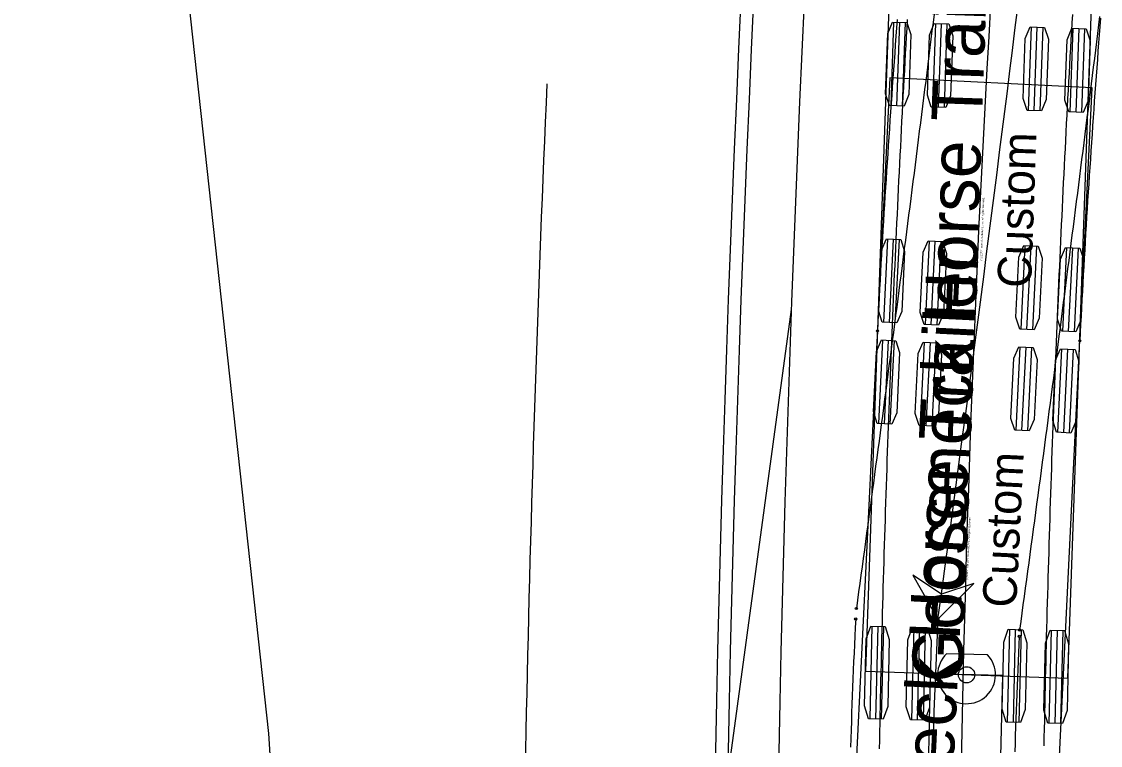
# Model space of a CAD drawing. Extents: x -14 to 1565148, y -25 to 642856.
# Drawn here: x 1564745.69 to 1564788.3, y 636164.84 to 636193.41 of the extents above; entities that cross this region are included whole.
import ezdxf

# ---------------------------------------------------------------- set-up
doc = ezdxf.new("R2010")
doc.units = 0
for name, color, linetype in [('CM_Corridor_Key_Station', 7, 'Continuous'), ('DR_P_Underdrain', 7, 'Continuous'), ('PV_P_EOP', 7, 'Continuous'), ('PV_X_EOP', 7, 'Continuous'), ('SC_Scratch15', 7, 'Continuous'), ('SC_Scratch2', 7, 'Continuous'), ('TR_Turning_Path24', 7, 'Continuous')]:
    doc.layers.add(name, color=color, linetype=linetype)

msp = doc.modelspace()

# ---------------------------------------------------------------- linework, layer by layer
at = {"layer": 'CM_Corridor_Key_Station'}
for p, q in [((1564779.982, 636191.188), (1564778.215, 636155.232)), ((1564787.972, 636190.795), (1564779.982, 636191.188)), ((1564786.206, 636154.839), (1564787.972, 636190.795)), ((1564779.737, 636181.539), (1564779.899, 636184.835)), ((1564779.966, 636181.527), (1564780.128, 636184.823)), ((1564780.195, 636181.516), (1564780.357, 636184.812)), ((1564781.385, 636181.458), (1564781.547, 636184.754)), ((1564781.614, 636181.446), (1564781.776, 636184.742)), ((1564781.843, 636181.435), (1564782.005, 636184.731)), ((1564785.164, 636181.272), (1564785.326, 636184.568)), ((1564785.393, 636181.261), (1564785.555, 636184.557)), ((1564785.622, 636181.249), (1564785.784, 636184.545)), ((1564786.812, 636181.191), (1564786.974, 636184.487)), ((1564787.041, 636181.18), (1564787.203, 636184.476)), ((1564787.27, 636181.168), (1564787.432, 636184.464)), ((1564779.541, 636177.543), (1564779.703, 636180.839)), ((1564779.77, 636177.532), (1564779.932, 636180.828)), ((1564779.999, 636177.521), (1564780.161, 636180.817)), ((1564781.189, 636177.462), (1564781.351, 636180.758)), ((1564781.418, 636177.451), (1564781.58, 636180.747)), ((1564781.647, 636177.44), (1564781.809, 636180.736)), ((1564784.968, 636177.277), (1564785.13, 636180.573)), ((1564785.197, 636177.265), (1564785.359, 636180.561)), ((1564785.426, 636177.254), (1564785.587, 636180.55)), ((1564786.616, 636177.196), (1564786.778, 636180.492)), ((1564786.845, 636177.184), (1564787.007, 636180.48)), ((1564787.074, 636177.173), (1564787.236, 636180.469))]:
    msp.add_line(p, q, dxfattribs=at)
for points in [[(1564781.726, 636193.711), (1564781.685, 636193.38), (1564781.644, 636193.049), (1564781.602, 636192.718), (1564781.561, 636192.388), (1564781.519, 636192.057), (1564781.478, 636191.726), (1564781.437, 636191.395), (1564781.395, 636191.064), (1564781.353, 636190.734), (1564781.312, 636190.403), (1564781.27, 636190.072), (1564781.228, 636189.741), (1564781.186, 636189.411), (1564781.144, 636189.08), (1564781.102, 636188.749), (1564781.06, 636188.418), (1564781.018, 636188.088), (1564780.976, 636187.757), (1564780.934, 636187.426), (1564780.892, 636187.095), (1564780.849, 636186.765), (1564780.807, 636186.434), (1564780.764, 636186.103), (1564780.722, 636185.773), (1564780.679, 636185.442), (1564780.637, 636185.111), (1564780.594, 636184.781), (1564780.551, 636184.45), (1564780.508, 636184.12), (1564780.465, 636183.789), (1564780.423, 636183.458), (1564780.38, 636183.128), (1564780.337, 636182.797), (1564780.293, 636182.467), (1564780.25, 636182.136), (1564780.207, 636181.805), (1564780.164, 636181.475), (1564780.12, 636181.144), (1564780.077, 636180.814), (1564780.034, 636180.483), (1564779.99, 636180.153), (1564779.946, 636179.822), (1564779.903, 636179.492), (1564779.859, 636179.161), (1564779.815, 636178.831), (1564779.772, 636178.5), (1564779.728, 636178.17), (1564779.684, 636177.839), (1564779.64, 636177.509), (1564779.596, 636177.178), (1564779.552, 636176.848), (1564779.507, 636176.517), (1564779.463, 636176.187), (1564779.419, 636175.856), (1564779.375, 636175.526), (1564779.33, 636175.196), (1564779.286, 636174.865), (1564779.241, 636174.535), (1564779.197, 636174.204), (1564779.152, 636173.874), (1564779.107, 636173.544), (1564779.063, 636173.213), (1564779.018, 636172.883), (1564778.973, 636172.552), (1564778.928, 636172.222), (1564778.883, 636171.892), (1564778.838, 636171.561), (1564778.793, 636171.231), (1564778.748, 636170.901), (1564778.702, 636170.57), (1564778.657, 636170.24)], [(1564780.269, 636193.494), (1564780.244, 636193.163), (1564780.22, 636192.832), (1564780.195, 636192.5), (1564780.171, 636192.169), (1564780.147, 636191.837), (1564780.123, 636191.505), (1564780.099, 636191.174), (1564780.075, 636190.842), (1564780.052, 636190.51), (1564780.029, 636190.178), (1564780.006, 636189.846), (1564779.983, 636189.514), (1564779.96, 636189.182), (1564779.938, 636188.85), (1564779.916, 636188.518), (1564779.894, 636188.186), (1564779.872, 636187.854), (1564779.851, 636187.522), (1564779.829, 636187.189), (1564779.808, 636186.857), (1564779.788, 636186.525), (1564779.767, 636186.192), (1564779.747, 636185.86), (1564779.727, 636185.527), (1564779.707, 636185.194), (1564779.687, 636184.862), (1564779.668, 636184.529), (1564779.649, 636184.196), (1564779.63, 636183.864), (1564779.612, 636183.531), (1564779.594, 636183.198), (1564779.576, 636182.865), (1564779.558, 636182.532), (1564779.541, 636182.199), (1564779.524, 636181.866), (1564779.508, 636181.533), (1564779.491, 636181.2)], [(1564788.263, 636193.609), (1564788.222, 636193.277), (1564788.181, 636192.945), (1564788.139, 636192.613), (1564788.098, 636192.281), (1564788.056, 636191.949), (1564788.015, 636191.617), (1564787.973, 636191.285), (1564787.932, 636190.953), (1564787.89, 636190.621), (1564787.849, 636190.289), (1564787.807, 636189.957), (1564787.765, 636189.625), (1564787.723, 636189.293), (1564787.681, 636188.962), (1564787.639, 636188.63), (1564787.597, 636188.298), (1564787.555, 636187.966), (1564787.513, 636187.634), (1564787.47, 636187.302), (1564787.428, 636186.97), (1564787.386, 636186.638), (1564787.343, 636186.307), (1564787.301, 636185.975), (1564787.258, 636185.643), (1564787.216, 636185.311), (1564787.173, 636184.979), (1564787.13, 636184.647), (1564787.088, 636184.316), (1564787.045, 636183.984), (1564787.002, 636183.652), (1564786.959, 636183.32), (1564786.916, 636182.989), (1564786.873, 636182.657), (1564786.83, 636182.325), (1564786.787, 636181.993), (1564786.743, 636181.662), (1564786.7, 636181.33), (1564786.657, 636180.998), (1564786.613, 636180.666), (1564786.57, 636180.335), (1564786.526, 636180.003), (1564786.483, 636179.671), (1564786.439, 636179.34), (1564786.395, 636179.008), (1564786.351, 636178.676), (1564786.308, 636178.345), (1564786.264, 636178.013), (1564786.22, 636177.681), (1564786.176, 636177.35), (1564786.132, 636177.018), (1564786.088, 636176.686), (1564786.043, 636176.355), (1564785.999, 636176.023), (1564785.955, 636175.692), (1564785.91, 636175.36), (1564785.866, 636175.028), (1564785.821, 636174.697), (1564785.777, 636174.365), (1564785.732, 636174.034), (1564785.688, 636173.702), (1564785.643, 636173.371), (1564785.598, 636173.039), (1564785.553, 636172.708), (1564785.508, 636172.376), (1564785.463, 636172.044), (1564785.418, 636171.713), (1564785.373, 636171.381), (1564785.328, 636171.05), (1564785.283, 636170.719), (1564785.238, 636170.387), (1564785.192, 636170.056), (1564785.147, 636169.724), (1564785.102, 636169.393)], [(1564788.296, 636193.55), (1564788.271, 636193.223), (1564788.246, 636192.895), (1564788.222, 636192.567), (1564788.198, 636192.239), (1564788.174, 636191.912), (1564788.15, 636191.584), (1564788.126, 636191.257), (1564788.102, 636190.929), (1564788.079, 636190.602), (1564788.055, 636190.275), (1564788.032, 636189.947), (1564788.009, 636189.62), (1564787.987, 636189.293), (1564787.964, 636188.966), (1564787.942, 636188.639), (1564787.92, 636188.312), (1564787.898, 636187.985), (1564787.876, 636187.658), (1564787.855, 636187.332), (1564787.834, 636187.005), (1564787.813, 636186.678), (1564787.792, 636186.352), (1564787.772, 636186.025), (1564787.752, 636185.699), (1564787.732, 636185.372), (1564787.712, 636185.046), (1564787.693, 636184.72), (1564787.674, 636184.393), (1564787.655, 636184.067), (1564787.636, 636183.741), (1564787.618, 636183.415), (1564787.6, 636183.089), (1564787.582, 636182.763), (1564787.565, 636182.437), (1564787.547, 636182.111), (1564787.53, 636181.785), (1564787.514, 636181.459), (1564787.498, 636181.133), (1564787.482, 636180.808)], [(1564781.879, 636169.816), (1564783.301, 636171.223), (1564782.015, 636170.807), (1564780.889, 636171.554), (1564781.879, 636169.816)], [(1564778.632, 636169.829), (1564778.615, 636169.492), (1564778.598, 636169.155), (1564778.581, 636168.818), (1564778.566, 636168.482), (1564778.551, 636168.145), (1564778.536, 636167.808), (1564778.522, 636167.471), (1564778.509, 636167.134), (1564778.496, 636166.797), (1564778.484, 636166.46), (1564778.472, 636166.123), (1564778.461, 636165.786), (1564778.451, 636165.449), (1564778.441, 636165.112), (1564778.431, 636164.775)], [(1564785.092, 636169.143), (1564785.076, 636168.818), (1564785.06, 636168.492), (1564785.045, 636168.166), (1564785.03, 636167.841), (1564785.016, 636167.515), (1564785.003, 636167.189), (1564784.99, 636166.863), (1564784.978, 636166.538), (1564784.966, 636166.212), (1564784.955, 636165.886), (1564784.944, 636165.56), (1564784.934, 636165.234), (1564784.924, 636164.908), (1564784.915, 636164.582)]]:
    msp.add_lwpolyline(points, dxfattribs=at)
for points in [[(1564780.252, 636181.513), (1564779.681, 636181.541), (1564779.531, 636182.011), (1564779.648, 636184.384), (1564779.842, 636184.837), (1564780.414, 636184.809), (1564780.563, 636184.339), (1564780.447, 636181.966)], [(1564781.9, 636181.432), (1564781.329, 636181.46), (1564781.179, 636181.93), (1564781.296, 636184.303), (1564781.49, 636184.756), (1564782.062, 636184.728), (1564782.211, 636184.258), (1564782.095, 636181.885)], [(1564785.679, 636181.247), (1564785.107, 636181.275), (1564784.958, 636181.745), (1564785.074, 636184.118), (1564785.269, 636184.571), (1564785.841, 636184.543), (1564785.99, 636184.073), (1564785.873, 636181.7)], [(1564787.327, 636181.166), (1564786.755, 636181.194), (1564786.606, 636181.664), (1564786.722, 636184.037), (1564786.917, 636184.49), (1564787.489, 636184.462), (1564787.638, 636183.992), (1564787.521, 636181.619)], [(1564780.056, 636177.518), (1564779.484, 636177.546), (1564779.335, 636178.016), (1564779.451, 636180.389), (1564779.646, 636180.842), (1564780.217, 636180.814), (1564780.367, 636180.344), (1564780.25, 636177.971)], [(1564781.704, 636177.437), (1564781.132, 636177.465), (1564780.983, 636177.935), (1564781.099, 636180.308), (1564781.294, 636180.761), (1564781.865, 636180.733), (1564782.015, 636180.263), (1564781.898, 636177.89)], [(1564785.482, 636177.251), (1564784.911, 636177.279), (1564784.762, 636177.749), (1564784.878, 636180.122), (1564785.073, 636180.575), (1564785.644, 636180.547), (1564785.794, 636180.078), (1564785.677, 636177.704)], [(1564787.13, 636177.17), (1564786.559, 636177.198), (1564786.41, 636177.668), (1564786.526, 636180.042), (1564786.721, 636180.494), (1564787.292, 636180.466), (1564787.442, 636179.997), (1564787.325, 636177.623)], [(1564781.879, 636169.816), (1564783.301, 636171.223), (1564782.015, 636170.807), (1564780.889, 636171.554)]]:
    msp.add_lwpolyline(points, close=True, dxfattribs=at)
for centre in [(1564779.491, 636181.2), (1564787.482, 636180.808), (1564778.657, 636170.24), (1564778.632, 636169.829), (1564781.879, 636169.816), (1564781.879, 636169.816), (1564785.092, 636169.143), (1564785.102, 636169.393)]:
    msp.add_circle(centre, 0.0417, dxfattribs=at)
for centre, radius, start, end in [((1562925.521, 636424.468), 1873.744, 352.189039, 353.77192), ((1564973.133, 636159.58), 191.527, 176.93628, 185.6665)]:
    msp.add_arc(centre, radius, start, end, dxfattribs=at)
at = {"layer": 'DR_P_Underdrain'}
msp.add_arc((1565825.386, 636143.743), 1060, 177.447513, 180.049148, dxfattribs=at)
at = {"layer": 'PV_P_EOP'}
for radius in [1052.5, 1052]:
    msp.add_arc((1565825.386, 636143.743), radius, 173.149636, 180.049148, dxfattribs=at)
at = {"layer": 'PV_X_EOP'}
msp.add_arc((1565825.386, 636143.743), 1050, 173.149636, 180.049148, dxfattribs=at)
at = {"layer": 'SC_Scratch15'}
msp.add_line((1564776.085, 636182.048), (1564749.532, 635987.025), dxfattribs=at)
at = {"layer": 'SC_Scratch2'}
msp.add_lwpolyline([(1564754.004, 636104.365), (1564754.004, 636104.365), (1564754.117, 636105.834), (1564756.989, 636126.551), (1564757.34, 636135.563), (1564755.452, 636165.307), (1564749.612, 636218.853), (1564749.948, 636242.687), (1564750.674, 636329.64), (1564750.409, 636437.843), (1564745.69, 636447.055)], dxfattribs=at)
at = {"layer": 'TR_Turning_Path24'}
for p, q in [((1564780.276, 636203.745), (1564779.013, 636167.767)), ((1564787.008, 636167.486), (1564788.271, 636203.464)), ((1564780.026, 636190.095), (1564780.142, 636193.393)), ((1564780.255, 636190.087), (1564780.371, 636193.385)), ((1564780.484, 636190.079), (1564780.6, 636193.377)), ((1564781.675, 636190.037), (1564781.791, 636193.335)), ((1564781.904, 636190.029), (1564782.02, 636193.327)), ((1564782.133, 636190.021), (1564782.249, 636193.319)), ((1564785.456, 636189.904), (1564785.572, 636193.202)), ((1564785.685, 636189.896), (1564785.801, 636193.194)), ((1564785.914, 636189.888), (1564786.03, 636193.186)), ((1564787.105, 636189.846), (1564787.221, 636193.144)), ((1564787.334, 636189.838), (1564787.45, 636193.136)), ((1564787.563, 636189.83), (1564787.679, 636193.128)), ((1564779.197, 636165.883), (1564779.284, 636169.549)), ((1564779.426, 636165.878), (1564779.513, 636169.543)), ((1564779.655, 636165.872), (1564779.742, 636169.538)), ((1564780.847, 636165.844), (1564780.934, 636169.51)), ((1564781.076, 636165.838), (1564781.163, 636169.504)), ((1564781.305, 636165.833), (1564781.392, 636169.499)), ((1564784.629, 636165.754), (1564784.716, 636169.42)), ((1564784.858, 636165.749), (1564784.945, 636169.414)), ((1564785.087, 636165.743), (1564785.174, 636169.409)), ((1564786.278, 636165.715), (1564786.365, 636169.38)), ((1564786.507, 636165.709), (1564786.595, 636169.375)), ((1564786.737, 636165.704), (1564786.824, 636169.37)), ((1564783.837, 636168.415), (1564782.222, 636168.453)), ((1564779.013, 636167.767), (1564787.008, 636167.486)), ((1564781.577, 636167.66), (1564781.34, 636157.663)), ((1564784.443, 636167.592), (1564781.577, 636167.66)), ((1564784.206, 636157.595), (1564784.443, 636167.592)), ((1564787.008, 636167.486), (1564787.008, 636167.486))]:
    msp.add_line(p, q, dxfattribs=at)
for points in [[(1564780.666, 636193.49), (1564780.647, 636193.156), (1564780.628, 636192.821), (1564780.609, 636192.487), (1564780.591, 636192.153), (1564780.572, 636191.818), (1564780.554, 636191.484), (1564780.535, 636191.149), (1564780.517, 636190.815), (1564780.499, 636190.48), (1564780.482, 636190.146), (1564780.464, 636189.811), (1564780.446, 636189.477), (1564780.429, 636189.142), (1564780.412, 636188.808), (1564780.395, 636188.473), (1564780.378, 636188.139), (1564780.361, 636187.804), (1564780.344, 636187.47), (1564780.328, 636187.135), (1564780.312, 636186.801), (1564780.295, 636186.466), (1564780.279, 636186.132), (1564780.263, 636185.797), (1564780.248, 636185.462), (1564780.232, 636185.128), (1564780.217, 636184.793), (1564780.201, 636184.459), (1564780.186, 636184.124), (1564780.171, 636183.789), (1564780.156, 636183.455), (1564780.142, 636183.12), (1564780.127, 636182.786), (1564780.113, 636182.451), (1564780.098, 636182.116), (1564780.084, 636181.782), (1564780.07, 636181.447), (1564780.056, 636181.112), (1564780.043, 636180.778), (1564780.029, 636180.443), (1564780.016, 636180.108), (1564780.002, 636179.774), (1564779.989, 636179.439), (1564779.976, 636179.104), (1564779.963, 636178.769), (1564779.951, 636178.435), (1564779.938, 636178.1), (1564779.926, 636177.765), (1564779.914, 636177.431), (1564779.902, 636177.096), (1564779.89, 636176.761), (1564779.878, 636176.426), (1564779.866, 636176.092), (1564779.855, 636175.757), (1564779.843, 636175.422), (1564779.832, 636175.087), (1564779.821, 636174.753), (1564779.81, 636174.418), (1564779.8, 636174.083), (1564779.789, 636173.748), (1564779.778, 636173.413), (1564779.768, 636173.079), (1564779.758, 636172.744), (1564779.748, 636172.409), (1564779.738, 636172.074), (1564779.728, 636171.739), (1564779.719, 636171.405), (1564779.709, 636171.07), (1564779.7, 636170.735), (1564779.691, 636170.4), (1564779.682, 636170.065), (1564779.673, 636169.73), (1564779.664, 636169.396), (1564779.656, 636169.061), (1564779.647, 636168.726), (1564779.639, 636168.391), (1564779.631, 636168.056), (1564779.623, 636167.721), (1564779.615, 636167.387), (1564779.608, 636167.052), (1564779.6, 636166.717), (1564779.593, 636166.382), (1564779.585, 636166.047), (1564779.578, 636165.712), (1564779.571, 636165.377), (1564779.565, 636165.042), (1564779.558, 636164.708)], [(1564787.188, 636193.692), (1564787.169, 636193.361), (1564787.15, 636193.029), (1564787.131, 636192.698), (1564787.112, 636192.366), (1564787.093, 636192.035), (1564787.075, 636191.703), (1564787.056, 636191.371), (1564787.038, 636191.04), (1564787.02, 636190.708), (1564787.002, 636190.377), (1564786.985, 636190.045), (1564786.967, 636189.713), (1564786.949, 636189.382), (1564786.932, 636189.05), (1564786.915, 636188.718), (1564786.898, 636188.387), (1564786.881, 636188.055), (1564786.864, 636187.723), (1564786.848, 636187.392), (1564786.831, 636187.06), (1564786.815, 636186.728), (1564786.799, 636186.397), (1564786.783, 636186.065), (1564786.767, 636185.733), (1564786.751, 636185.401), (1564786.736, 636185.07), (1564786.72, 636184.738), (1564786.705, 636184.406), (1564786.69, 636184.074), (1564786.675, 636183.743), (1564786.66, 636183.411), (1564786.645, 636183.079), (1564786.631, 636182.747), (1564786.616, 636182.415), (1564786.602, 636182.084), (1564786.588, 636181.752), (1564786.574, 636181.42), (1564786.56, 636181.088), (1564786.546, 636180.756), (1564786.533, 636180.425), (1564786.519, 636180.093), (1564786.506, 636179.761), (1564786.493, 636179.429), (1564786.48, 636179.097), (1564786.467, 636178.765), (1564786.455, 636178.434), (1564786.442, 636178.102), (1564786.43, 636177.77), (1564786.417, 636177.438), (1564786.405, 636177.106), (1564786.393, 636176.774), (1564786.382, 636176.442), (1564786.37, 636176.11), (1564786.358, 636175.778), (1564786.347, 636175.447), (1564786.336, 636175.115), (1564786.325, 636174.783), (1564786.314, 636174.451), (1564786.303, 636174.119), (1564786.293, 636173.787), (1564786.282, 636173.455), (1564786.272, 636173.123), (1564786.262, 636172.791), (1564786.252, 636172.459), (1564786.242, 636172.127), (1564786.232, 636171.795), (1564786.222, 636171.463), (1564786.213, 636171.131), (1564786.203, 636170.799), (1564786.194, 636170.467), (1564786.185, 636170.135), (1564786.176, 636169.803), (1564786.168, 636169.471), (1564786.159, 636169.139), (1564786.151, 636168.807), (1564786.142, 636168.475), (1564786.134, 636168.143), (1564786.126, 636167.811), (1564786.118, 636167.479), (1564786.111, 636167.147), (1564786.103, 636166.815), (1564786.096, 636166.483), (1564786.088, 636166.151), (1564786.081, 636165.819), (1564786.074, 636165.487), (1564786.067, 636165.155), (1564786.061, 636164.823)]]:
    msp.add_lwpolyline(points, dxfattribs=at)
for points in [[(1564780.541, 636190.077), (1564779.969, 636190.097), (1564779.813, 636190.565), (1564779.897, 636192.939), (1564780.085, 636193.395), (1564780.657, 636193.375), (1564780.813, 636192.907), (1564780.729, 636190.532)], [(1564782.19, 636190.019), (1564781.618, 636190.039), (1564781.462, 636190.507), (1564781.546, 636192.881), (1564781.734, 636193.337), (1564782.306, 636193.317), (1564782.462, 636192.849), (1564782.378, 636190.475)], [(1564785.971, 636189.886), (1564785.399, 636189.906), (1564785.243, 636190.374), (1564785.327, 636192.749), (1564785.515, 636193.204), (1564786.087, 636193.184), (1564786.243, 636192.716), (1564786.159, 636190.342)], [(1564787.62, 636189.828), (1564787.048, 636189.848), (1564786.892, 636190.316), (1564786.976, 636192.691), (1564787.164, 636193.146), (1564787.736, 636193.126), (1564787.892, 636192.658), (1564787.808, 636190.284)], [(1564779.712, 636165.871), (1564779.14, 636165.884), (1564778.98, 636166.402), (1564779.043, 636169.041), (1564779.227, 636169.55), (1564779.799, 636169.536), (1564779.959, 636169.019), (1564779.897, 636166.38)], [(1564781.362, 636165.832), (1564780.79, 636165.845), (1564780.63, 636166.363), (1564780.692, 636169.002), (1564780.877, 636169.511), (1564781.449, 636169.497), (1564781.609, 636168.98), (1564781.546, 636166.341)], [(1564785.144, 636165.742), (1564784.572, 636165.755), (1564784.412, 636166.273), (1564784.475, 636168.912), (1564784.659, 636169.421), (1564785.231, 636169.407), (1564785.391, 636168.89), (1564785.328, 636166.251)], [(1564786.793, 636165.703), (1564786.222, 636165.716), (1564786.061, 636166.233), (1564786.124, 636168.873), (1564786.309, 636169.382), (1564786.88, 636169.368), (1564787.041, 636168.851), (1564786.978, 636166.212)]]:
    msp.add_lwpolyline(points, close=True, dxfattribs=at)
msp.add_circle((1564783.01, 636167.626), 0.32, dxfattribs=at)
for centre, radius, start, end in [((1565542.412, 636149.749), 759.751, 173.572806, 179.735174), ((1564783.01, 636167.626), 1.143, 133.6391, 43.6391)]:
    msp.add_arc(centre, radius, start, end, dxfattribs=at)

# ---------------------------------------------------------------- texts
at = {"layer": 'CM_Corridor_Key_Station'}
for s, height, p in [('Gooseneck Horse Trailer', 2, (1564782.034, 636154.71)), ('Custom', 1.3333, (1564784.967, 636170.252)), ('(c) 2022 Transoft Solutions, Inc. All rights reserved.', 0.08, (1564783.053, 636171.375))]:
    msp.add_text(s, height=height, rotation=87.1869, dxfattribs=at).set_placement(p)
at = {"layer": 'TR_Turning_Path24'}
for s, height, p in [('Gooseneck Horse Trailer', 2, (1564782.839, 636167.299)), ('Custom', 1.3333, (1564785.554, 636182.88)), ('(c) 2022 Transoft Solutions, Inc. All rights reserved.', 0.08, (1564783.624, 636183.977))]:
    msp.add_text(s, height=height, rotation=87.9893, dxfattribs=at).set_placement(p)

doc.saveas('drawing.dxf')
